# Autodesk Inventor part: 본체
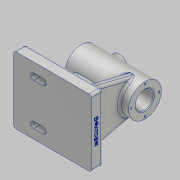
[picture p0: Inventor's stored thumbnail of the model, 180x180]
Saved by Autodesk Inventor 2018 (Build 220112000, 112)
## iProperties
Created: 2022-06
Part Number: 본체
Material: 알루미늄 6061
Document SubType Name: Modeling
Designer: home
Density: 2.7 g/cm^3
Appearance: 알루미늄 - 평지
Mass: 632.935 g
Surface Area: 512.719 cm^2
Volume: 234.42 cm^3
Author: home
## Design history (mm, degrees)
sketch "스케치1"
  geometry: L1 (50, -43)-(-50, -43); L2 (-50, -43)-(-50, 43); L3 (-50, 43)-(50, 43); L4 (50, 43)-(50, -43); 3 further points
  constraints: 8 end point, 2 midpoint, 2 parallel, 1 horizontal, 1 horizontal alignment, 1 perpendicular, 1 vertical alignment
  dimensions: "d0" = 100 distance of L1.start L1.end; "d1" = 86 distance of L3.end L1.start
extrude "돌출1" new body sketch "스케치1" distance "d2" = 15; taper "d3" = 0 deg
sketch "스케치2"
  geometry: L1 (-71.574, 72)-(71.574, 72); L2 (-50, 0)-(50, 0) reference; L3 (-35, 86.5)-(27, 86.5); L4 (27, 86.5)-(27, 83.5); L5 (27, 83.5)-(47, 83.5); L6 (47, 83.5)-(47, 93); L7 (47, 93)-(-35, 93); L8 (-35, 93)-(-35, 86.5); L9 (-50, 0)-(-50, 15) reference; 2 further points
  constraints: 14 end point, 5 perpendicular, 2 horizontal, 1 midpoint, 1 vertical alignment
  dimensions: "d4" = 72 distance between parallel lines of L2 L1; "d5" = 15 distance between parallel lines of L9 L8; "d6" = 82 distance of L6.end L7.end; "d7" = 23 diameter of L5 L1; "d9" = 42 diameter of L7 L1; "d10" = 29 diameter of L3 L1; "d11" = 20 distance between parallel lines of L6 L4; "d12" = 121.57388 distance from line of L1.end L9
revolve "회전1" sketch "스케치2" stored, may be unused: angle "d13" = 90 deg
sketch "스케치3"
  geometry: L1 (-24, 27)-(-12, 27); L2 (-24, 20)-(-12, 20); L3 (-12, 34)-(-24, 34); L4 (-50, 43)-(50, 43) reference; L5 (-50, -43)-(-50, 43) reference; A1 r 7 centre (-24, 27) between (-24, 34) and (-24, 20); A2 r 7 centre (-12, 27) between (-12, 20) and (-12, 34); 2 further points
  constraints: 8 end point, 4 point on circle, 4 tangent, 2 centre point, 1 horizontal, 1 midpoint, 1 parallel
  dimensions: "d14" = 12 distance of L1.start L1.end; "d15" = 7 radius of A2; "d80" = 26 distance from line of L5 L1.start; "d81" = 16 distance between parallel lines of L4 L1
extrude "돌출2" join sketch "스케치3" distance "d18" = 3; taper "d19" = 0 deg
sketch "스케치4"
  geometry: L1 (-24, 34)-(-12, 34) reference; L2 (-12, 20)-(-24, 20) reference; L3 (50, 43)-(-50, 43) reference; L4 (-50, 43)-(-50, -43) reference; L5 (-50, -43)-(50, -43) reference; L6 (50, -43)-(50, 43) reference; L7 (-24, 27)-(-12, 27); L8 (-24, 23)-(-12, 23); L9 (-12, 31)-(-24, 31); A1 r 7 centre (-24, 27) between (-24, 34) and (-24, 20) reference; A2 r 7 centre (-12, 27) between (-12, 20) and (-12, 34) reference; A3 r 4 centre (-24, 27) between (-24, 31) and (-24, 23); A4 r 4 centre (-12, 27) between (-12, 23) and (-12, 31); 2 further points
  constraints: 8 end point, 4 point on circle, 4 tangent, 2 centre point, 1 horizontal, 1 midpoint, 1 parallel
  dimensions: "d20" = 4 radius of A4
extrude "돌출3" cut sketch "스케치4" extent not by distance; stored distance "d21" = 3; taper "d22" = 0 deg
fillet "모깎기1" dims "d26" = 3
fillet "모깎기2" dims "d27" = 3
sketch "스케치5"
  geometry: C1 r 11.5 at (0, 0) reference; 2 further points
  constraints: 1 vertical alignment
  dimensions: "d28" = 18 distance of C1.centre point (0, 18)
hole "구멍1" sketch "스케치5" at (0, 18) diameter "d29" = 2.459; stored, may be unused: countersink angle "d33" = 90 deg, drill point angle "d35" = 118 deg; dims "d30" = 8, "d31" = 4, "d32" = 2, "d34" = 10
node "작업 평면1"
node "작업 평면2"
sketch "스케치6"
  geometry: L1 (19, 72)-(5, 15); L2 (61, 72)-(75, 15); L3 (23, 15)-(3, 15) reference; L4 (77, 15)-(57, 15) reference; L5 (-3, 0)-(-3, 12) reference; L6 (83, 12)-(83, 0) reference; L7 (5, 15)-(75, 15); A1 r 21 centre (40, 72) between (19, 72) and (61, 72) reference; 1 further point
  constraints: 6 end point, 2 horizontal alignment, 2 point on circle, 2 point on line, 1 collinear
  dimensions: "d40" = 8 distance from line of L1.end L5; "d41" = 8 distance from line of L6 L2.end
extrude "돌출4" join sketch "스케치6" distance "d42" = 10; taper "d43" = 0 deg
sketch "스케치7"
  geometry: L1 (-21.897, 51)-(-35, 15); L2 (-47, 15)-(47, 15) reference; L3 (-35, 51)-(47, 51) reference; L4 (-24, 15)-(-34, 15) reference; L5 (-24, 15)-(-12, 15) reference; L6 (-50, 0)-(-50, 12) reference; 1 further point
  constraints: 2 end point, 2 point on line
  dimensions: "d44" = 70 deg angle of L2 L1; "d45" = 15 distance from line of L6 L1.end
feature "리브1" sketch "스케치7" dims "d46" = 1, "d47" = 10, "d48" = 0, "d49" = 0, "d50" = 1, "d51" = 1
fillet "모깎기3" dims "d52" = 3
fillet "모깎기4" dims "d53" = 3
node "작업 평면3"
sketch "스케치8"
  geometry: L1 (35, 21)-(35, -21) reference; C1 r 11 at (10, 0); 1 further point
  constraints: 1 centre point, 1 horizontal alignment
  dimensions: "d55" = 11 radius of C1; "d56" = 25 distance from line of L1 C1.centre
extrude "돌출5" join sketch "스케치8" stored distance "d57" = 10; taper "d58" = 0 deg; dims "d4" = 72, "d5" = 15, "d6" = 82, "d7" = 23, "d9" = 42, "d10" = 29, "d11" = 20, "d12" = 121.57388
sketch "스케치9"
  geometry: C1 r 11 at (0, 0) reference; C2 r 7 at (0, 0); 1 further point
  constraints: 1 centre point, 1 coincident
  dimensions: "d59" = 7 radius of C2
extrude "돌출7" cut sketch "스케치9" distance "d62" = 4; taper "d63" = 0 deg
sketch "스케치10"
  geometry: C1 r 7 at (0, 0) reference; 2 further points
  constraints: 1 coincident
hole "구멍2" sketch "스케치10" at (0, 0) diameter "d64" = 6; stored, may be unused: countersink angle "d68" = 90 deg, drill point angle "d70" = 0 deg; dims "d65" = 8, "d66" = 4, "d67" = 2, "d69" = 10
feature "스레드1" dims "d71" = 10, "d72" = 0
fillet "모깎기5" dims "d73" = 1
chamfer "모따기1" distance "d74" = 1; stored, may be unused: second distance "d75" = 2, angle "d76" = 45 deg
sketch "스케치11"
  geometry: L1 (80, 0)-(0, 0) reference; 3 further points
  constraints: 1 midpoint, 1 vertical alignment, 1 other
  dimensions: "d77" = 6 distance from line of L1 point (40, 6)
feature "엠보싱1" sketch "스케치11" dims "d0" = 100, "d1" = 86, "d78" = 0.5, "d79" = 0
node "솔리드1"
pattern_linear "직사각형 패턴1" dims "d25" = 54
pattern_circular "원형 패턴1" dims angle "d37" = 360 deg
mirror "미러1"
node "투영된 루프1"
node "투영된 루프2"
node "투영된 루프3"
other parameters: "d39" = -15, "d54" = 96
